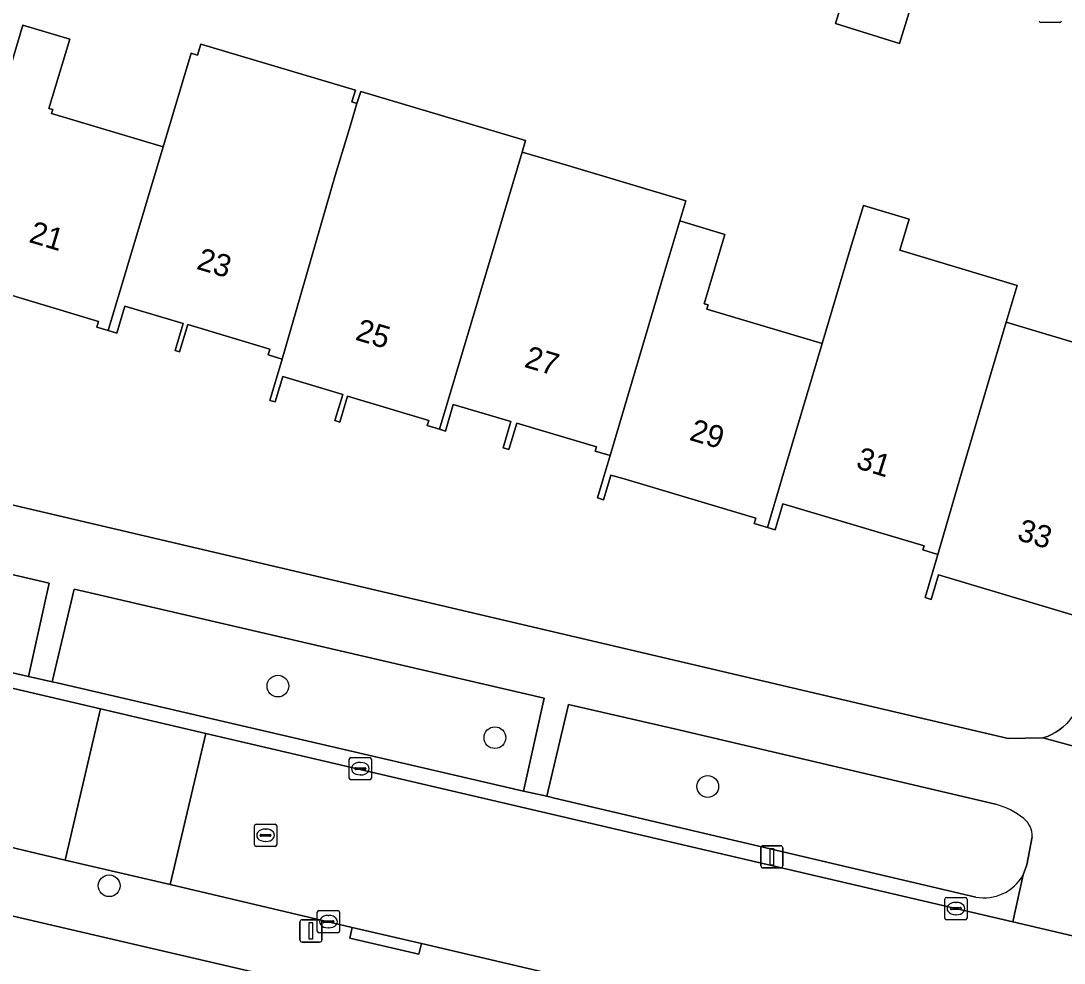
# Model space of a CAD drawing. Extents: x 162184 to 163154, y 385507 to 386516.
# Drawn here: x 162712.42 to 162759.38, y 385978.22 to 386020.61 of the extents above; entities that cross this region are included whole.
import ezdxf

# ---------------------------------------------------------------- set-up
doc = ezdxf.new("R2010")
doc.units = 0
for name, color, linetype in [('IMGEO_Boom', 7, 'Continuous'), ('IMGEO_Erf', 7, 'Continuous'), ('IMGEO_Groenvoorziening', 7, 'Continuous'), ('IMGEO_Kolk', 7, 'Continuous'), ('IMGEO_Lichtmast', 7, 'Continuous'), ('IMGEO_Pand', 7, 'Continuous'), ('IMGEO_Pand_nummerreeks', 7, 'Continuous'), ('IMGEO_Rijbaan_lokaal_open', 7, 'Continuous'), ('IMGEO_Rioolput', 7, 'Continuous'), ('IMGEO_Voetpad_open', 7, 'Continuous')]:
    doc.layers.add(name, color=color, linetype=linetype)

msp = doc.modelspace()

# ---------------------------------------------------------------- linework, layer by layer
at = {"layer": 'IMGEO_Boom'}
for centre in [(162723.99, 385990.683), (162733.758, 385988.359), (162743.336, 385986.163), (162716.396, 385981.697)]:
    msp.add_circle(centre, 0.489, dxfattribs=at)
at = {"layer": 'IMGEO_Erf'}
msp.add_lwpolyline([(162749.081, 386020.489), (162749.952, 386023.313), (162752.837, 386022.423), (162751.966, 386019.599)], close=True, dxfattribs=at)
for points in [[(162708.771, 386007.883), (162712.514, 386020.419), (162714.618, 386019.79), (162713.686, 386016.67), (162713.857, 386016.619), (162713.804, 386016.441), (162718.824, 386014.942), (162720.084, 386019.161), (162720.374, 386019.074), (162720.521, 386019.567), (162727.483, 386017.488), (162727.315, 386016.968), (162727.55, 386016.892), (162727.726, 386017.437), (162735.139, 386015.223), (162734.986, 386014.71), (162737.034, 386014.099), (162742.349, 386012.514), (162742.079, 386011.606), (162744.111, 386011), (162743.181, 386007.885), (162743.355, 386007.833), (162743.299, 386007.643), (162748.49, 386006.093), (162749.725, 386010.228), (162750.346, 386012.308), (162752.405, 386011.694), (162751.985, 386010.287), (162757.262, 386008.711), (162756.767, 386007.055), (162764.485, 386004.751)], [(162783.536, 385963.718), (162627.446, 386000), (162549.733, 386018.064)], [(162760.852, 385993.551), (162753.724, 385995.68), (162753.397, 385994.582), (162753.119, 385994.665), (162753.695, 385996.604), (162753.018, 385996.805), (162753.072, 385996.985), (162746.72, 385998.882), (162746.373, 385997.718), (162746.02, 385997.823), (162745.431, 385997.999), (162745.5, 385998.23), (162739.571, 386000), (162738.981, 386000.176), (162738.928, 386000), (162738.649, 385999.065), (162738.376, 385999.146), (162738.631, 386000), (162738.945, 386001.056), (162738.274, 386001.256), (162738.33, 386001.443), (162734.741, 386002.514), (162734.384, 386001.32), (162734.122, 386001.398), (162734.475, 386002.581), (162731.886, 386003.354), (162731.529, 386002.157), (162731.26, 386002.237), (162730.711, 386002.401), (162730.781, 386002.637), (162727.122, 386003.73), (162726.773, 386002.56), (162726.557, 386002.624), (162726.909, 386003.803), (162724.209, 386004.609), (162723.869, 386003.467), (162723.632, 386003.537), (162724.185, 386005.396), (162723.549, 386005.585), (162723.625, 386005.84), (162719.93, 386006.944), (162719.565, 386005.723), (162719.364, 386005.783), (162719.725, 386006.993), (162717.095, 386007.778), (162716.733, 386006.565), (162716.356, 386006.677), (162715.841, 386006.831), (162715.918, 386007.089), (162709.48, 386009.012)], [(162707.015, 386000), (162756.863, 385988.324), (162758.422, 385988.351), (162758.623, 385988.418), (162758.816, 385988.502), (162759.002, 385988.603), (162759.178, 385988.72), (162759.342, 385988.853), (162759.495, 385988.999)]]:
    msp.add_lwpolyline(points, dxfattribs=at)
at = {"layer": 'IMGEO_Groenvoorziening'}
for points in [[(162679.477, 385998.729), (162712.765, 385991.116), (162713.694, 385995.315), (162700.057, 385998.495)], [(162741.841, 385988.756), (162737.327, 385989.791), (162737.067, 385989.851), (162736.098, 385985.722), (162736.436, 385985.643), (162755.401, 385981.189)], [(162756.296, 385985.362), (162741.841, 385988.756)], [(162757.537, 385982.185), (162757.702, 385982.634), (162757.945, 385983.903)]]:
    msp.add_lwpolyline(points, dxfattribs=at)
msp.add_lwpolyline([(162715.089, 385994.98), (162714.817, 385995.043), (162713.837, 385990.871), (162714.109, 385990.807), (162735.04, 385985.953), (162735.982, 385990.138)], close=True, dxfattribs=at)
for centre, radius, start, end in [((162755.407, 385982.038), 3.441, 51.2941, 75.0328), ((162756.896, 385983.91), 1.049, 359.6249, 50.7908), ((162755.781, 385983.163), 2.01, 259.1103, 330.8883)]:
    msp.add_arc(centre, radius, start, end, dxfattribs=at)
at = {"layer": 'IMGEO_Kolk'}
for p, q in [((162759.183, 386020.536), (162758.331, 386020.536)), ((162727.2, 385986.539), (162727.2, 385987.391)), ((162727.275, 385987.465), (162728.127, 385987.465)), ((162728.201, 385987.391), (162728.201, 385986.539)), ((162727.459, 385986.959), (162727.459, 385986.971)), ((162727.897, 385986.922), (162727.499, 385986.922)), ((162727.502, 385987.008), (162727.9, 385987.008)), ((162727.688, 385987.245), (162727.713, 385987.245)), ((162727.943, 385986.971), (162727.943, 385986.959)), ((162728.127, 385986.465), (162727.275, 385986.465)), ((162727.711, 385986.685), (162727.686, 385986.685)), ((162754.007, 385980.243), (162754.007, 385981.095)), ((162754.082, 385981.169), (162754.934, 385981.169)), ((162754.309, 385980.712), (162754.707, 385980.712)), ((162754.495, 385980.949), (162754.52, 385980.949)), ((162755.008, 385981.095), (162755.008, 385980.243)), ((162725.764, 385979.656), (162725.764, 385980.508)), ((162725.839, 385980.582), (162726.691, 385980.582)), ((162726.252, 385980.362), (162726.277, 385980.362)), ((162726.765, 385980.508), (162726.765, 385979.656)), ((162754.266, 385980.663), (162754.266, 385980.675)), ((162754.704, 385980.626), (162754.306, 385980.626)), ((162754.518, 385980.389), (162754.493, 385980.389)), ((162754.75, 385980.675), (162754.75, 385980.663)), ((162726.023, 385980.076), (162726.023, 385980.088)), ((162726.461, 385980.039), (162726.063, 385980.039)), ((162726.066, 385980.125), (162726.464, 385980.125)), ((162726.275, 385979.802), (162726.25, 385979.802)), ((162726.507, 385980.088), (162726.507, 385980.076)), ((162754.934, 385980.169), (162754.082, 385980.169)), ((162726.691, 385979.582), (162725.839, 385979.582))]:
    msp.add_line(p, q, dxfattribs=at)
for points in [[(162759.183, 386020.536), (162758.331, 386020.536)], [(162727.2, 385986.539), (162727.2, 385987.391)], [(162727.275, 385987.465), (162728.127, 385987.465)], [(162728.201, 385987.391), (162728.201, 385986.539)], [(162728.127, 385986.465), (162727.275, 385986.465)], [(162754.007, 385980.243), (162754.007, 385981.095)], [(162754.082, 385981.169), (162754.934, 385981.169)], [(162755.008, 385981.095), (162755.008, 385980.243)], [(162725.764, 385979.656), (162725.764, 385980.508)], [(162725.839, 385980.582), (162726.691, 385980.582)], [(162726.765, 385980.508), (162726.765, 385979.656)], [(162754.934, 385980.169), (162754.082, 385980.169)], [(162726.691, 385979.582), (162725.839, 385979.582)]]:
    msp.add_lwpolyline(points, dxfattribs=at)
for centre, radius, start, end in [((162758.333, 386020.612), 0.0765, 181.552, 268.448), ((162758.333, 386020.612), 0.0765, 181.552, 268.448), ((162759.181, 386020.612), 0.0765, 271.552, 358.448), ((162759.181, 386020.612), 0.0765, 271.552, 358.448), ((162727.277, 385987.389), 0.0765, 91.552, 178.448), ((162727.277, 385987.389), 0.0765, 91.552, 178.448), ((162728.125, 385987.389), 0.0765, 1.552, 88.448), ((162728.125, 385987.389), 0.0765, 1.552, 88.448), ((162727.499, 385986.968), 0.0403, 85.8775, 175.7526), ((162727.496, 385986.958), 0.0366, 178.938, 274.7102), ((162727.9, 385986.965), 0.043, 264.8664, 352.4533), ((162727.904, 385986.97), 0.0386, 1.7309, 96.639), ((162727.277, 385986.541), 0.0765, 181.552, 268.448), ((162727.277, 385986.541), 0.0765, 181.552, 268.448), ((162728.125, 385986.541), 0.0765, 271.552, 358.448), ((162728.125, 385986.541), 0.0765, 271.552, 358.448), ((162754.084, 385981.093), 0.0765, 91.552, 178.448), ((162754.084, 385981.093), 0.0765, 91.552, 178.448), ((162754.306, 385980.672), 0.0403, 85.8775, 175.7526), ((162754.711, 385980.674), 0.0386, 1.7309, 96.639), ((162754.932, 385981.093), 0.0765, 1.552, 88.448), ((162754.932, 385981.093), 0.0765, 1.552, 88.448), ((162725.841, 385980.506), 0.0765, 91.552, 178.448), ((162725.841, 385980.506), 0.0765, 91.552, 178.448), ((162726.689, 385980.506), 0.0765, 1.552, 88.448), ((162726.689, 385980.506), 0.0765, 1.552, 88.448), ((162754.084, 385980.245), 0.0765, 181.552, 268.448), ((162754.084, 385980.245), 0.0765, 181.552, 268.448), ((162754.303, 385980.662), 0.0366, 178.938, 274.7102), ((162754.707, 385980.669), 0.043, 264.8664, 352.4533), ((162754.932, 385980.245), 0.0765, 271.552, 358.448), ((162754.932, 385980.245), 0.0765, 271.552, 358.448), ((162726.063, 385980.085), 0.0403, 85.8775, 175.7526), ((162726.06, 385980.075), 0.0366, 178.938, 274.7102), ((162726.464, 385980.082), 0.043, 264.8664, 352.4533), ((162726.468, 385980.087), 0.0386, 1.7309, 96.639), ((162725.841, 385979.658), 0.0765, 181.552, 268.448), ((162725.841, 385979.658), 0.0765, 181.552, 268.448), ((162726.689, 385979.658), 0.0765, 271.552, 358.448), ((162726.689, 385979.658), 0.0765, 271.552, 358.448)]:
    msp.add_arc(centre, radius, start, end, dxfattribs=at)
for centre, major_axis, ratio, start_param, end_param in [((162727.687, 385986.965), (-0.387, 0.002), 0.722429, 4.712389, 7.853982), ((162727.712, 385986.965), (-0.39, 0.002), 0.717154, 1.570796, 4.712389), ((162754.494, 385980.669), (-0.387, 0.002), 0.722429, 4.712389, 7.853982), ((162754.519, 385980.669), (-0.39, 0.002), 0.717154, 1.570796, 4.712389), ((162726.251, 385980.082), (-0.387, 0.002), 0.722429, 4.712389, 7.853982), ((162726.276, 385980.082), (-0.39, 0.002), 0.717154, 1.570796, 4.712389)]:
    msp.add_ellipse(centre, major_axis=major_axis, ratio=ratio, start_param=start_param, end_param=end_param, dxfattribs=at)
at = {"layer": 'IMGEO_Lichtmast'}
for p, q in [((162745.727, 385982.596), (162745.727, 385983.396)), ((162745.727, 385983.396), (162745.727, 385982.596)), ((162745.827, 385983.496), (162746.617, 385983.496)), ((162746.617, 385983.496), (162745.827, 385983.496)), ((162746.717, 385983.396), (162746.717, 385982.596)), ((162746.717, 385982.596), (162746.717, 385983.396)), ((162746.617, 385982.496), (162745.827, 385982.496)), ((162745.827, 385982.496), (162746.617, 385982.496)), ((162724.979, 385979.265), (162724.979, 385980.065)), ((162724.979, 385980.065), (162724.979, 385979.265)), ((162725.079, 385980.165), (162725.869, 385980.165)), ((162725.869, 385980.165), (162725.079, 385980.165)), ((162725.969, 385980.065), (162725.969, 385979.265)), ((162725.969, 385979.265), (162725.969, 385980.065)), ((162725.869, 385979.165), (162725.079, 385979.165)), ((162725.079, 385979.165), (162725.869, 385979.165))]:
    msp.add_line(p, q, dxfattribs=at)
for points in [[(162746.147, 385983.371), (162746.297, 385983.371), (162746.297, 385982.621), (162746.147, 385982.621), (162746.147, 385983.371)], [(162725.399, 385980.04), (162725.549, 385980.04), (162725.549, 385979.29), (162725.399, 385979.29), (162725.399, 385980.04)]]:
    msp.add_lwpolyline(points, dxfattribs=at)
for centre, start, end in [((162745.827, 385983.396), 90, 180), ((162745.827, 385983.396), 90, 180), ((162746.617, 385983.396), 0, 90), ((162746.617, 385983.396), 360, 90), ((162745.827, 385982.596), 180, 270), ((162745.827, 385982.596), 180, 270), ((162746.617, 385982.596), 270, 0), ((162746.617, 385982.596), 270, 0), ((162725.079, 385980.065), 90, 180), ((162725.079, 385980.065), 90, 180), ((162725.869, 385980.065), 0, 90), ((162725.869, 385980.065), 360, 90), ((162725.079, 385979.265), 180, 270), ((162725.079, 385979.265), 180, 270), ((162725.869, 385979.265), 270, 0), ((162725.869, 385979.265), 270, 0)]:
    msp.add_arc(centre, 0.1, start, end, dxfattribs=at)
at = {"layer": 'IMGEO_Pand'}
for points in [[(162749.081, 386020.489), (162751.966, 386019.599), (162752.837, 386022.423), (162749.952, 386023.313)], [(162718.824, 386014.942), (162713.804, 386016.441), (162713.857, 386016.619), (162713.686, 386016.67), (162714.618, 386019.79), (162712.514, 386020.419), (162708.771, 386007.883), (162709.112, 386007.781), (162709.48, 386009.012), (162715.918, 386007.089), (162715.841, 386006.831), (162716.356, 386006.677)], [(162726.561, 386013.653), (162727.253, 386015.92), (162727.55, 386016.892), (162727.315, 386016.968), (162727.483, 386017.488), (162720.521, 386019.567), (162720.374, 386019.074), (162720.084, 386019.161), (162718.824, 386014.942), (162716.356, 386006.677), (162716.733, 386006.565), (162717.095, 386007.778), (162719.725, 386006.993), (162719.364, 386005.783), (162719.565, 386005.723), (162719.93, 386006.944), (162723.625, 386005.84), (162723.549, 386005.585), (162724.185, 386005.396)], [(162733.719, 386010.468), (162734.986, 386014.71), (162735.139, 386015.223), (162727.726, 386017.437), (162727.55, 386016.892), (162727.253, 386015.92), (162726.561, 386013.653), (162724.185, 386005.396), (162723.632, 386003.537), (162723.869, 386003.467), (162724.209, 386004.609), (162726.909, 386003.803), (162726.557, 386002.624), (162726.773, 386002.56), (162727.122, 386003.73), (162730.781, 386002.637), (162730.711, 386002.401), (162731.26, 386002.237)], [(162741.367, 386009.209), (162742.079, 386011.606), (162742.349, 386012.514), (162737.034, 386014.099), (162734.986, 386014.71), (162733.719, 386010.468), (162731.26, 386002.237), (162731.529, 386002.157), (162731.886, 386003.354), (162734.475, 386002.581), (162734.122, 386001.398), (162734.384, 386001.32), (162734.741, 386002.514), (162738.33, 386001.443), (162738.274, 386001.256), (162738.945, 386001.056)], [(162756.102, 386004.828), (162756.767, 386007.055), (162757.262, 386008.711), (162751.985, 386010.287), (162752.405, 386011.694), (162750.346, 386012.308), (162749.725, 386010.228), (162748.49, 386006.093), (162746.67, 386000), (162746.02, 385997.823), (162746.373, 385997.718), (162746.72, 385998.882), (162753.072, 385996.985), (162753.018, 385996.805), (162753.695, 385996.604), (162754.688, 386000)], [(162748.49, 386006.093), (162743.299, 386007.643), (162743.355, 386007.833), (162743.181, 386007.885), (162744.111, 386011), (162742.079, 386011.606), (162741.367, 386009.209), (162738.945, 386001.056), (162738.631, 386000), (162738.376, 385999.146), (162738.649, 385999.065), (162738.928, 386000), (162738.981, 386000.176), (162739.571, 386000), (162745.5, 385998.23), (162745.431, 385997.999), (162746.02, 385997.823), (162746.67, 386000)], [(162763.067, 386000), (162764.485, 386004.751), (162756.767, 386007.055), (162756.102, 386004.828), (162754.688, 386000), (162753.695, 385996.604), (162753.119, 385994.665), (162753.397, 385994.582), (162753.724, 385995.68), (162760.852, 385993.551), (162760.793, 385993.355), (162761.059, 385993.276)]]:
    msp.add_lwpolyline(points, close=True, dxfattribs=at)
at = {"layer": 'IMGEO_Rijbaan_lokaal_open'}
for points in [[(162671.697, 386000), (162653.515, 386004.211), (162635.584, 386008.379), (162633.981, 386001.479), (162638.145, 386000.504), (162640.314, 386000), (162644.966, 385998.919), (162652.104, 385997.26), (162660.336, 385995.367), (162667.647, 385993.685), (162682.431, 385990.285), (162687.936, 385989.019), (162705.604, 385984.92), (162709.674, 385983.966), (162714.417, 385982.854), (162716.011, 385989.658)], [(162720.741, 385988.554), (162716.011, 385989.658), (162714.417, 385982.854), (162719.147, 385981.746)]]:
    msp.add_lwpolyline(points, close=True, dxfattribs=at)
msp.add_lwpolyline([(162765.095, 385978.24), (162759.758, 385979.448), (162757.068, 385980.076), (162720.741, 385988.554), (162719.147, 385981.746), (162727.339, 385979.826), (162730.448, 385979.097), (162742.931, 385976.169), (162746.702, 385975.285), (162751.636, 385974.128), (162755.187, 385973.295), (162786.628, 385966.226)], dxfattribs=at)
at = {"layer": 'IMGEO_Rioolput'}
for p, q in [((162723.01, 385984.467), (162723.862, 385984.467)), ((162722.935, 385983.541), (162722.935, 385984.393)), ((162723.237, 385984.01), (162723.635, 385984.01)), ((162723.423, 385984.247), (162723.448, 385984.247)), ((162723.936, 385984.393), (162723.936, 385983.541)), ((162723.194, 385983.961), (162723.194, 385983.973)), ((162723.632, 385983.924), (162723.234, 385983.924)), ((162723.446, 385983.687), (162723.421, 385983.687)), ((162723.678, 385983.973), (162723.678, 385983.961)), ((162723.862, 385983.467), (162723.01, 385983.467))]:
    msp.add_line(p, q, dxfattribs=at)
for points in [[(162723.01, 385984.467), (162723.862, 385984.467)], [(162722.935, 385983.541), (162722.935, 385984.393)], [(162723.936, 385984.393), (162723.936, 385983.541)], [(162723.862, 385983.467), (162723.01, 385983.467)]]:
    msp.add_lwpolyline(points, dxfattribs=at)
for centre, radius, start, end in [((162723.012, 385984.391), 0.0765, 91.552, 178.448), ((162723.012, 385984.391), 0.0765, 91.552, 178.448), ((162723.86, 385984.391), 0.0765, 1.552, 88.448), ((162723.86, 385984.391), 0.0765, 1.552, 88.448), ((162723.234, 385983.97), 0.0403, 85.8775, 175.7526), ((162723.639, 385983.972), 0.0386, 1.7309, 96.639), ((162723.012, 385983.543), 0.0765, 181.552, 268.448), ((162723.012, 385983.543), 0.0765, 181.552, 268.448), ((162723.231, 385983.96), 0.0366, 178.938, 274.7102), ((162723.635, 385983.967), 0.043, 264.8664, 352.4533), ((162723.86, 385983.543), 0.0765, 271.552, 358.448), ((162723.86, 385983.543), 0.0765, 271.552, 358.448)]:
    msp.add_arc(centre, radius, start, end, dxfattribs=at)
for centre, major_axis, ratio, start_param, end_param in [((162723.422, 385983.967), (-0.387, 0.002), 0.722429, 4.712389, 7.853982), ((162723.447, 385983.967), (-0.39, 0.002), 0.717154, 1.570796, 4.712389)]:
    msp.add_ellipse(centre, major_axis=major_axis, ratio=ratio, start_param=start_param, end_param=end_param, dxfattribs=at)
at = {"layer": 'IMGEO_Voetpad_open'}
for points in [[(162769.309, 386021.056), (162768.405, 386018.122), (162764.485, 386004.751), (162763.067, 386000), (162761.059, 385993.276), (162760.014, 385989.856), (162759.955, 385989.703), (162759.864, 385989.512), (162759.757, 385989.331), (162759.633, 385989.159), (162759.495, 385988.999), (162759.342, 385988.853), (162759.178, 385988.72), (162759.002, 385988.603), (162758.816, 385988.502), (162758.623, 385988.418), (162758.422, 385988.351), (162762.348, 385987.291), (162766.162, 386000), (162772.997, 386022.928)], [(162549.733, 386018.064), (162627.446, 386000), (162783.536, 385963.718)], [(162757.945, 385983.903), (162757.702, 385982.634), (162757.537, 385982.185), (162757.068, 385980.076), (162759.758, 385979.448), (162759.873, 385979.94), (162765.2, 385978.691), (162767.082, 385985.941), (162762.348, 385987.291), (162758.422, 385988.351), (162756.863, 385988.324), (162707.015, 386000), (162696.564, 386002.448), (162682.926, 386005.689), (162674.38, 386007.643), (162659.17, 386011.222)], [(162679.477, 385998.729), (162679.372, 385998.748), (162672.499, 386000.509), (162672.324, 386000.567), (162654.412, 386004.751), (162653.515, 386004.211), (162671.697, 386000), (162716.011, 385989.658), (162720.741, 385988.554), (162757.068, 385980.076), (162757.537, 385982.185)], [(162680.572, 386003.053), (162693.533, 386000), (162700.057, 385998.495), (162713.694, 385995.315), (162712.765, 385991.116), (162713.837, 385990.871), (162714.817, 385995.043), (162715.089, 385994.98), (162735.982, 385990.138), (162735.04, 385985.953), (162736.098, 385985.722), (162737.067, 385989.851), (162737.327, 385989.791), (162741.841, 385988.756), (162756.296, 385985.362)], [(162755.401, 385981.189), (162736.436, 385985.643), (162736.098, 385985.722), (162735.04, 385985.953), (162714.109, 385990.807), (162713.837, 385990.871), (162712.765, 385991.116), (162679.477, 385998.729)], [(162786.628, 385966.226), (162755.187, 385973.295), (162755.073, 385972.809), (162751.522, 385973.641), (162751.636, 385974.128), (162746.702, 385975.285), (162746.587, 385974.799), (162742.816, 385975.684), (162742.931, 385976.169), (162730.448, 385979.097), (162730.334, 385978.615), (162727.225, 385979.344), (162727.339, 385979.826), (162719.147, 385981.746), (162714.417, 385982.854), (162709.674, 385983.966)]]:
    msp.add_lwpolyline(points, dxfattribs=at)
msp.add_lwpolyline([(162730.448, 385979.097), (162727.339, 385979.826), (162727.225, 385979.344), (162730.334, 385978.615)], close=True, dxfattribs=at)
for centre, radius, start, end in [((162755.407, 385982.038), 3.441, 51.2941, 75.0328), ((162756.896, 385983.91), 1.049, 359.6249, 50.7908), ((162755.781, 385983.163), 2.01, 259.1103, 330.8883)]:
    msp.add_arc(centre, radius, start, end, dxfattribs=at)

# ---------------------------------------------------------------- texts
at = {"layer": 'IMGEO_Pand_nummerreeks'}
for s, rotation, p in [('21', 343.3694, (162712.737, 386010.669)), ('23', 343.4702, (162720.284, 386009.46)), ('25', 343.2983, (162727.428, 386006.275)), ('27', 343.4816, (162735.032, 386005.05)), ('29', 343.3785, (162742.464, 386001.766)), ('31', 342.5592, (162749.959, 386000.507)), ('33', 343.3701, (162757.218, 385997.267))]:
    msp.add_text(s, height=1, rotation=rotation, dxfattribs=at).set_placement(p)

doc.saveas('drawing.dxf')
